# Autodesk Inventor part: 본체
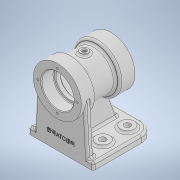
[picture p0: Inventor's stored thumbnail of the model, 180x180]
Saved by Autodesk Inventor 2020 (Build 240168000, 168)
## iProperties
Created: 2024-02
Part Number: 본체
Material: 일반
Document SubType Name: Modeling
Designer: oem
Density: 1 g/cm^3
Appearance: 기본값
Author: oem
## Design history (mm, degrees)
sketch "스케치1"
  geometry: C1 r 35 at (0, 0); 1 further point
  constraints: 1 centre point, 1 coincident
  dimensions: "d0" = 70 diameter of C1
extrude "돌출1" new body sketch "스케치1" stored distance "d1" = 78; taper "d2" = 0 deg
sketch "스케치2"
  geometry: L1 (35, 39)-(-35, 39) reference; L2 (-35, -39)-(35, -39) reference; L3 (0, 39)-(0, -39); L4 (35, 17)-(28.5, 17); L5 (28.5, -17)-(35, -17); L6 (35, 17)-(28.5, 17); L7 (28.5, 17)-(28.5, -17); L8 (28.5, -17)-(35, -17); L9 (35, -17)-(35, 17); L10 (0, -54.6)-(0, 54.6) reference; 2 further points
  constraints: 14 end point, 2 horizontal, 2 midpoint, 2 parallel, 1 perpendicular
  dimensions: "d4" = 22 distance between parallel lines of L1 L4; "d5" = 22 distance between parallel lines of L2 L5; "d6" = 28.5 distance between parallel lines of L7 L3
revolve "회전1" sketch "스케치2" stored, may be unused: angle "d7" = 90 deg
node "작업 평면1"
sketch "스케치3"
  geometry: C1 r 6 at (0, 0); 1 further point
  constraints: 1 centre point, 1 coincident
  dimensions: "d9" = 12 diameter of C1
extrude "돌출2" join sketch "스케치3" stored distance "d10" = 78; taper "d11" = 0 deg
sketch "스케치4"
  geometry: L1 (35, 39)-(-35, 39) reference; L2 (0, 39)-(23.5, 39); L3 (23.5, 39)-(23.5, 21); L4 (23.5, 21)-(0, 21); L5 (0, 21)-(0, 39); L6 (0, 21)-(20, 21); L7 (20, 21)-(20, 15.208); L8 (20, 15.208)-(0, 15.208); L9 (0, 15.208)-(0, 21); L10 (0, 15.208)-(20.5, 15.208); L11 (23.5, 12.208)-(23.5, -11.792); L12 (20.5, -14.792)-(0, -14.792); L13 (0, -14.792)-(0, 15.208); L14 (0, -14.792)-(20, -14.792); L15 (20, -14.792)-(20, -21); L16 (20, -21)-(0, -21); L17 (0, -21)-(0, -14.792); L18 (-35, -39)-(35, -39) reference; L19 (0, -21)-(23.5, -21); L20 (23.5, -21)-(23.5, -39); L21 (23.5, -39)-(0, -39); L22 (0, -39)-(0, -21); A1 r 3 centre (20.5, 12.208) between (23.5, 12.208) and (20.5, 15.208); A2 r 3 centre (20.5, -11.792) between (20.5, -14.792) and (23.5, -11.792); 7 further points
  constraints: 40 end point, 10 parallel, 5 horizontal, 5 perpendicular, 4 point on circle, 4 tangent, 2 centre point, 1 equal radius, 1 midpoint, 1 point on line
  dimensions: "d12" = 47 diameter of L3 L5; "d13" = 40 diameter of L7 L9; "d14" = 47 diameter of L11 L13; "d15" = 40 diameter of L15 L17; "d16" = 47 diameter of L20 L22; "d17" = 3 radius of A1; "d116" = 18 distance of L2.end L3.end; "d117" = 30 distance between parallel lines of L12 L8; "d118" = 18 distance between parallel lines of L21 L16
revolve "회전2" sketch "스케치4" stored, may be unused: angle "d18" = 90 deg
sketch "스케치5"
  geometry: C1 r 6 at (0, 0) reference
hole "구멍1" sketch "스케치5" at (0, 0) diameter "d19" = 5.1881; stored, may be unused: countersink angle "d23" = 90 deg, drill point angle "d25" = 0 deg; dims "d20" = 30, "d21" = 7, "d22" = 2, "d24" = 35
node "작업 평면2"
sketch "스케치6"
  geometry: L1 (35, 39)-(-35, 39) reference; L2 (47, 34)-(-47, 34); L3 (-47, 34)-(-47, -56); L4 (-47, -56)-(47, -56); L5 (47, -56)-(47, 34); 1 further point
  constraints: 8 end point, 2 parallel, 1 horizontal, 1 perpendicular
  dimensions: "d27" = 5 distance between parallel lines of L1 L2; "d28" = 90 distance of L2.end L3.end; "d29" = 94 distance of L3.end L4.end; "d30" = 47 distance from line of L3 point (0, 0)
extrude "돌출3" join sketch "스케치6" distance "d31" = 10; taper "d32" = 0 deg
fillet "모깎기1" dims "d33" = 20
sketch "스케치7"
  geometry: C1 r 10 at (-27, 36); A1 r 20 centre (-27, 36) between (-27, 56) and (-47, 36) reference; 1 further point
  constraints: 1 centre point, 1 coincident
  dimensions: "d34" = 20 diameter of C1
extrude "돌출4" join sketch "스케치7" distance "d35" = 3; taper "d36" = 0 deg
sketch "스케치8"
  geometry: C1 r 10 at (0, 0) reference; 1 further point
hole "구멍2" sketch "스케치8" at (0, 0) diameter "d37" = 9; stored, may be unused: countersink angle "d41" = 90 deg, drill point angle "d43" = 0 deg; dims "d38" = 30, "d39" = 7, "d40" = 2, "d42" = 35
sketch "스케치9"
  geometry: L1 (-70, -36)-(-70, 34) reference; L2 (-70, 34)-(-31.183, 34); L3 (-31.183, -29.872)-(-70, -44); L4 (-70, -36)-(-70, -56) reference; L5 (-70, -56)-(-80, -56) reference; L6 (-31.183, 20.313)-(-26.863, 20.313); L7 (-26.863, 20.313)-(-26.863, -20.747); L8 (-26.863, -20.747)-(-31.183, -20.747); L9 (-31.183, 34)-(-31.183, 20.313); L10 (-31.183, -20.747)-(-31.183, -29.872); 1 further point
  constraints: 14 end point, 2 horizontal, 2 perpendicular, 2 vertical, 1 point on line
  dimensions: "d50" = 12 distance from line of L3.end L5; "d51" = 70 deg angle of L1 L3
extrude "돌출5" join sketch "스케치9" stored distance "d52" = 10; taper "d53" = 0 deg
sketch "스케치10"
  geometry: L1 (94, 0)-(94, 10) reference; L2 (52, 10)-(94, 10) reference; L3 (0, 10)-(42, 10) reference; L4 (0, 0)-(0, 10) reference; L5 (81.945, 81.969)-(86, 10); L6 (12.055, 81.969)-(8, 10); L7 (8, 10)-(86, 10); L8 (0, 10)-(20, 10) reference; A1 r 35 centre (47, 80) between (42, 45.359) and (52, 45.359) reference; A2 r 35 centre (47, 80) between (52, 45.359) and (42, 45.359) reference; 2 further points
  constraints: 6 end point, 2 point on circle, 2 point on line, 2 tangent, 1 collinear
  dimensions: "d54" = 8 distance from line of L1 L5.end; "d55" = 8 distance from line of L4 L6.end
extrude "돌출6" join sketch "스케치10" distance "d56" = 10; taper "d57" = 0 deg
sketch "스케치11"
  geometry: C1 r 35 at (0, 0) reference; A1 r 28.5 centre (0, 0) between (-5, -28.058) and (5, -28.058); A2 r 28.5 centre (0, 0) between (5, -28.058) and (-5, -28.058) reference; 1 further point
  constraints: 1 centre point, 1 coincident, 1 point on circle
  dimensions: "d58" = 57 diameter of A1
hole "구멍3" sketch "스케치11" at (0, 28.5) diameter "d59" = 3.242; stored, may be unused: countersink angle "d63" = 90 deg, drill point angle "d65" = 118 deg; dims "d60" = 8, "d61" = 7, "d62" = 2, "d64" = 10
node "작업 평면3"
chamfer "모따기1" distance "d74" = 1; stored, may be unused: second distance "d75" = 2, angle "d76" = 45 deg
fillet "모깎기7" dims "d77" = 3
fillet "모깎기8" dims "d78" = 3
fillet "모깎기9" dims "d79" = 1
fillet "모깎기12" dims "d85" = 3
fillet "모깎기24" dims "d103" = 3
fillet "모깎기29" dims "d108" = 3
fillet "모깎기32" dims "d111" = 3
fillet "모깎기33" dims "d112" = 3
sketch "스케치15"
  geometry: L1 (-44, -80)-(44, -80) reference; L2 (-25.274, -60)-(22.061, -60); L3 (-20.514, -56.819)-(20.965, -56.819); L4 (20.965, -56.819)-(20.965, -62.823); L5 (20.965, -62.823)-(-20.514, -62.823); L6 (-20.514, -62.823)-(-20.514, -56.819)
  constraints: 2 end point, 1 horizontal, 2 other
  dimensions: "d113" = 20 distance between parallel lines of L2 L1
feature "엠보싱4" sketch "스케치15" dims "d114" = 0.5, "d115" = 0
node "솔리드1"
pattern_linear "직사각형 패턴1" dims "d46" = 54, "d49" = 36
pattern_circular "원형 패턴1" dims angle "d67" = 360 deg
mirror "미러1"
feature "A9D066F2-1C7D-4E18-AEED-F7BC21143FA4" dims "d19" = 5.1881, "d20" = 30, "d21" = 7, "d22" = 2, "d23" = 90 deg, "d24" = 35, "d25" = 0
other parameters: "d8" = 31.5
